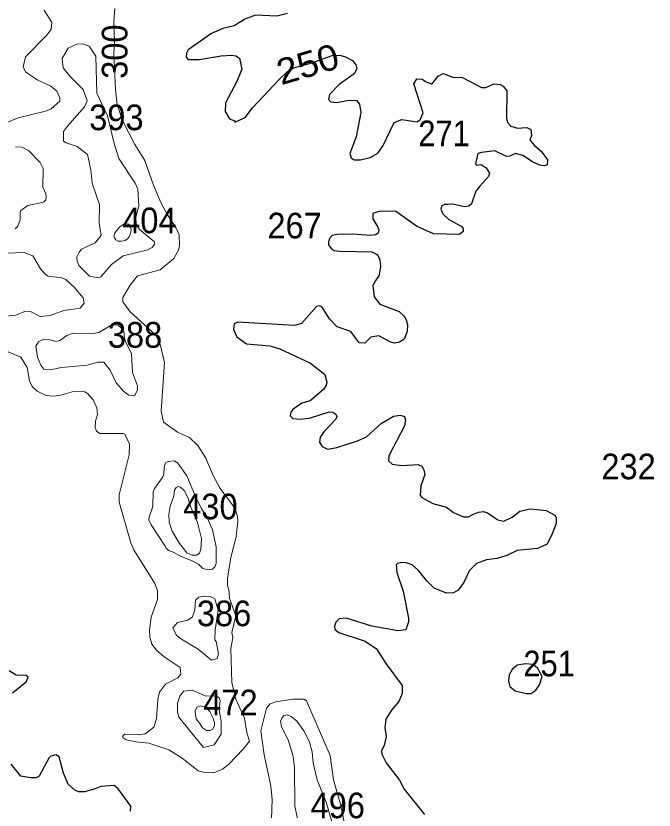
# Model space of a CAD drawing. Extents: x 499.9 to 555.3, y 9281.5 to 9336.8.
# Drawn here: x 510.006 to 513.988, y 9318.021 to 9322.977 of the extents above; entities that cross this region are included whole.
import ezdxf
from ezdxf.enums import TextEntityAlignment as Align

# ---------------------------------------------------------------- set-up
doc = ezdxf.new("R2010")
doc.units = 0
doc.header["$LTSCALE"] = 0.064
doc.layers.add('1', color=7, linetype='Continuous', lineweight=25)
doc.layers.add('2', color=7, linetype='Continuous', lineweight=13)
doc.layers.add('21', color=7, linetype='Continuous')
doc.layers.add('61', color=7, linetype='Continuous')

msp = doc.modelspace()

# ---------------------------------------------------------------- linework, layer by layer
at = {"layer": '1'}
for points in [[(511.7005, 9322.9921), (511.6328, 9322.9747), (511.5, 9322.9823), (511.4339, 9322.9573), (511.3669, 9322.9146), (511.2963, 9322.8996), (511.227, 9322.8667), (511.08, 9322.7658), (511.0698, 9322.7458), (511.0678, 9322.7203), (511.0805, 9322.7061), (511.1101, 9322.7058), (511.1499, 9322.7057), (511.2859, 9322.7292), (511.3514, 9322.7325), (511.3783, 9322.7279), (511.3998, 9322.7128), (511.4152, 9322.6445), (511.3837, 9322.5687), (511.3124, 9322.435), (511.3123, 9322.3802), (511.3385, 9322.3346), (511.3715, 9322.3222), (511.3721, 9322.3147), (511.4355, 9322.3441), (511.4815, 9322.4039), (511.6482, 9322.5815), (511.7006, 9322.6314), (511.7379, 9322.6543), (511.8526, 9322.6844), (511.9787, 9322.7308), (512.0276, 9322.7317), (512.0625, 9322.7222), (512.1062, 9322.6986), (512.1261, 9322.6727), (512.1321, 9322.6467), (512.1163, 9322.616), (512.0229, 9322.5493), (511.9632, 9322.4876), (511.9556, 9322.4558), (511.9703, 9322.4408), (512.0085, 9322.437), (512.0824, 9322.4508), (512.1299, 9322.4493), (512.1497, 9322.4261)], [(512.1163, 9322.0794), (512.1565, 9322.0789), (512.2161, 9322.093), (512.2646, 9322.1212), (512.2973, 9322.1677), (512.3656, 9322.3116), (512.4144, 9322.3313), (512.5066, 9322.316), (512.529, 9322.3298), (512.5466, 9322.3734), (512.4878, 9322.5543), (512.5065, 9322.5847), (512.5407, 9322.5828), (512.5648, 9322.5656), (512.6002, 9322.552), (512.6412, 9322.6003), (512.672, 9322.6176), (512.7319, 9322.5945), (512.7923, 9322.5939), (512.9101, 9322.5308), (512.9371, 9322.5308), (512.9872, 9322.5527), (513.027, 9322.5496), (513.0468, 9322.5399), (513.0694, 9322.5092), (513.0661, 9322.3386), (513.0727, 9322.3128), (513.0937, 9322.2897), (513.1361, 9322.2761), (513.1926, 9322.2807), (513.2183, 9322.2675), (513.2218, 9322.2314), (513.2117, 9322.2021), (513.2412, 9322.1677), (513.2834, 9322.1331), (513.3217, 9322.0792), (513.3199, 9322.0483), (513.3032, 9322.0422), (513.2754, 9322.0457), (513.2286, 9322.0665), (513.1693, 9322.1071), (513.1234, 9322.1179), (513.0858, 9322.1013), (513.0667, 9322.101), (512.9944, 9322.1356), (512.911, 9322.1251), (512.8885, 9322.1186), (512.8734, 9322.054), (512.8805, 9322.0458), (512.908, 9322.0502), (512.9392, 9322.0291), (512.9601, 9321.9951), (512.9542, 9321.9744), (512.9002, 9321.9139), (512.8745, 9321.8836), (512.8493, 9321.8045), (512.8316, 9321.7893), (512.8051, 9321.7859), (512.7319, 9321.803), (512.7008, 9321.8014), (512.6804, 9321.8009), (512.6622, 9321.7925), (512.6571, 9321.7722), (512.6696, 9321.7413), (512.7064, 9321.7077), (512.7846, 9321.6654), (512.7961, 9321.6515), (512.7966, 9321.6314), (512.773, 9321.6142), (512.6117, 9321.6169), (512.5059, 9321.6648), (512.3743, 9321.7598), (512.2703, 9321.7569), (512.2326, 9321.7439), (512.2326, 9321.7118), (512.2643, 9321.6587), (512.2696, 9321.641), (512.2667, 9321.6209), (512.2484, 9321.6115), (512.2178, 9321.6066), (512.1079, 9321.6154), (512.0103, 9321.6126), (511.9793, 9321.608), (511.9616, 9321.5891), (511.9551, 9321.5684), (511.9563, 9321.5478), (511.9734, 9321.5265), (511.9911, 9321.5135), (512.0285, 9321.5084), (512.2242, 9321.5053), (512.2497, 9321.4957), (512.2643, 9321.4834), (512.2758, 9321.4558), (512.2815, 9321.4135), (512.2722, 9321.3587)], [(512.1497, 9322.4261), (512.1578, 9322.3752), (512.1286, 9322.2228), (512.0893, 9322.1191), (512.0975, 9322.0927), (512.1163, 9322.0794)], [(512.2722, 9321.3587), (512.2505, 9321.3278), (512.2323, 9321.2945), (512.2417, 9321.2238), (512.2769, 9321.178), (512.3974, 9321.1329)], [(512.3974, 9321.1329), (512.4273, 9321.1034), (512.4413, 9321.0804), (512.4485, 9321.0496), (512.4479, 9321.0075), (512.4291, 9320.9599), (512.3987, 9320.9421), (512.3673, 9320.936), (512.3458, 9320.9414), (512.271, 9320.9816), (512.2196, 9320.972), (512.1832, 9320.9348), (512.147, 9320.9375), (512.0949, 9321.0072), (512.0094, 9321.0379), (511.9632, 9321.0871), (511.9374, 9321.1263), (511.9162, 9321.1604), (511.9015, 9321.1677), (511.8803, 9321.1641), (511.7885, 9321.0574), (511.7436, 9321.0445), (511.3892, 9321.0652), (511.3667, 9321.0548), (511.3634, 9321.0207), (511.3835, 9320.9748), (511.4451, 9320.9311), (511.5898, 9320.918), (511.6527, 9320.9006), (511.8444, 9320.8111), (511.9326, 9320.7399), (511.9453, 9320.6908), (511.9419, 9320.6725), (511.9242, 9320.6456), (511.8419, 9320.5756), (511.7897, 9320.56), (511.7347, 9320.5239), (511.7204, 9320.5042), (511.7169, 9320.4814), (511.7332, 9320.4648), (511.7746, 9320.4601), (511.8365, 9320.4678), (511.9607, 9320.5057), (511.9836, 9320.5042), (512.0023, 9320.4929), (512.0074, 9320.4783), (512.0016, 9320.4616), (511.9298, 9320.385), (511.9038, 9320.3478), (511.8989, 9320.3172), (511.9162, 9320.2908), (511.9424, 9320.2771), (511.9528, 9320.274), (512.0084, 9320.2847), (512.1373, 9320.325), (512.1937, 9320.3502), (512.2855, 9320.4339), (512.362, 9320.4801), (512.4039, 9320.4851), (512.4294, 9320.4778), (512.4371, 9320.4551), (512.4293, 9320.4202), (512.3333, 9320.2311), (512.331, 9320.2014), (512.3532, 9320.1801), (512.4126, 9320.1708), (512.516, 9320.1786), (512.5374, 9320.1669), (512.5502, 9320.1443), (512.5562, 9320.1165), (512.5329, 9320.0443), (512.5284, 9319.9841), (512.5378, 9319.9714), (512.6077, 9319.9348), (512.692, 9319.9122), (512.7351, 9319.8775), (512.7987, 9319.8506), (512.8289, 9319.8506), (512.8616, 9319.868), (512.8922, 9319.8807), (512.9228, 9319.8849), (512.9485, 9319.876), (512.9872, 9319.85), (513.0134, 9319.8328), (513.0501, 9319.8253), (513.101, 9319.8489), (513.149, 9319.8867), (513.2171, 9319.9023), (513.3142, 9319.892), (513.3682, 9319.8613), (513.3772, 9319.8467), (513.3764, 9319.8107), (513.3525, 9319.7454), (513.3198, 9319.6814), (513.261, 9319.6534)], [(513.261, 9319.6534), (513.1338, 9319.6419), (513.0692, 9319.61), (513.0055, 9319.591), (512.9412, 9319.5826), (512.8791, 9319.5608)], [(512.8791, 9319.5608), (512.8338, 9319.5144), (512.8013, 9319.4423), (512.7646, 9319.3937), (512.735, 9319.3763), (512.6917, 9319.3752), (512.6153, 9319.4071), (512.57, 9319.4519), (512.5185, 9319.5176), (512.478, 9319.5513), (512.4414, 9319.564), (512.4108, 9319.5662), (512.3861, 9319.5601), (512.3787, 9319.5518), (512.3822, 9319.5039), (512.421, 9319.3872), (512.4561, 9319.2189), (512.4547, 9319.1962), (512.4379, 9319.1454), (512.3904, 9319.1407), (512.227, 9319.1697), (512.0665, 9319.2198), (512.0217, 9319.2145), (512.002, 9319.1952), (511.9939, 9319.1698), (511.9957, 9319.1481), (512.0196, 9319.1291), (512.1843, 9319.0751), (512.2563, 9319.0269), (512.3144, 9318.936), (512.4163, 9318.7982), (512.4164, 9318.7491), (512.3946, 9318.6988), (512.3499, 9318.6455), (512.3135, 9318.5897), (512.307, 9318.5357), (512.3162, 9318.4816), (512.3035, 9318.4244), (512.2865, 9318.394), (512.2893, 9318.3709), (512.3154, 9318.3156), (512.3986, 9318.2085), (512.429, 9318.1522), (512.5546, 9317.9936)], [(509.9834, 9318.7536), (510.07, 9318.8218), (510.0812, 9318.8516), (510.0704, 9318.861), (510.0064, 9318.864), (509.9626, 9318.8909)], [(510.3986, 9318.1364), (510.3732, 9318.1459), (510.3315, 9318.1832), (510.3032, 9318.2524), (510.2749, 9318.354), (510.2543, 9318.3665), (510.2232, 9318.3581), (510.2114, 9318.3457), (510.1514, 9318.2339), (510.1318, 9318.2224), (510.0962, 9318.2222), (510.0359, 9318.2337), (509.9751, 9318.3073)], [(510.6447, 9318.1551), (510.6181, 9318.1757), (510.5345, 9318.1697), (510.4941, 9318.1522), (510.4329, 9318.1363), (510.3986, 9318.1364)], [(510.7214, 9318.0154), (510.723, 9318.0464), (510.6447, 9318.1551)]]:
    msp.add_lwpolyline(points, dxfattribs=at)
msp.add_lwpolyline([(513.2898, 9318.8542), (513.2616, 9318.906), (513.2339, 9318.9296), (513.1846, 9318.9343), (513.1335, 9318.9263), (513.1028, 9318.8987), (513.0834, 9318.8654), (513.0799, 9318.828), (513.0883, 9318.7928), (513.1203, 9318.7666), (513.1894, 9318.7492), (513.2181, 9318.7491), (513.2493, 9318.7689), (513.2719, 9318.8034)], close=True, dxfattribs=at)
at = {"layer": '2'}
for points in [[(510.1823, 9323.0126), (510.2292, 9322.9355), (510.2248, 9322.8935), (510.1947, 9322.852), (510.0645, 9322.7209), (510.0502, 9322.6602), (510.0646, 9322.6277), (510.139, 9322.5776), (510.2235, 9322.5383), (510.261, 9322.5086), (510.2795, 9322.4661), (510.2801, 9322.4457), (510.225, 9322.397), (510.191, 9322.3823), (510.0191, 9322.3409), (509.856, 9322.2749)], [(510.748, 9322.1758), (510.6723, 9322.3209), (510.6369, 9322.4223), (510.6268, 9322.5159), (510.6158, 9322.7446), (510.6216, 9322.8126), (510.6159, 9322.9429), (510.6236, 9323.0244)], [(511.0036, 9321.6576), (510.9521, 9321.7354), (510.9103, 9321.8128), (510.864, 9321.9209), (510.8104, 9322.076), (510.748, 9322.1758)], [(510.004, 9322.1595), (510.0452, 9322.1579), (510.0834, 9322.1373), (510.1565, 9322.0626), (510.1756, 9322.0261), (510.1742, 9321.9081), (510.192, 9321.8674), (510.1944, 9321.8469), (510.192, 9321.8291), (510.1781, 9321.8159), (510.081, 9321.7937), (510.036, 9321.7623), (510.0316, 9321.7506), (510.0324, 9321.7052), (510.0176, 9321.6659), (510.0019, 9321.6482)], [(510.2355, 9320.6048), (510.2776, 9320.6096), (510.3643, 9320.6334), (510.4349, 9320.631), (510.4527, 9320.6205), (510.487, 9320.5814), (510.5098, 9320.5315), (510.5144, 9320.4911), (510.5022, 9320.4495), (510.5005, 9320.4092), (510.5089, 9320.3871), (510.5285, 9320.3709), (510.6728, 9320.3721), (510.6849, 9320.3672), (510.7137, 9320.3056), (510.7121, 9320.2387), (510.6504, 9319.989), (510.6501, 9319.9434), (510.723, 9319.6888), (510.7416, 9319.6451), (510.8718, 9319.4349), (510.8885, 9319.3919), (510.8885, 9319.3362), (510.8506, 9319.2264), (510.8398, 9319.147), (510.8413, 9319.1016), (510.8541, 9319.0567), (510.882, 9319.0201), (510.9317, 9318.9779), (511.0309, 9318.9105), (511.0353, 9318.8691), (511.0154, 9318.8473), (510.9398, 9318.8076), (510.902, 9318.7574), (510.892, 9318.7139), (510.8827, 9318.5916), (510.8659, 9318.5399), (510.813, 9318.4964), (510.771, 9318.4912), (510.6859, 9318.4957), (510.6767, 9318.4895), (510.6717, 9318.4801), (510.6747, 9318.4722), (510.6926, 9318.4609), (510.7511, 9318.4469), (510.8354, 9318.44), (510.9588, 9318.3972), (511.0423, 9318.3459), (511.1435, 9318.2669), (511.1754, 9318.2583), (511.2413, 9318.254), (511.2946, 9318.2779), (511.335, 9318.3071), (511.4245, 9318.4011), (511.4628, 9318.4514), (511.4457, 9318.5032), (511.4313, 9318.5948), (511.3772, 9318.7147), (511.3537, 9318.8183), (511.3472, 9319.0291), (511.3597, 9319.0968), (511.3522, 9319.1294), (511.3787, 9319.2329), (511.3378, 9319.3447), (511.3373, 9319.3821), (511.3249, 9319.4278), (511.3249, 9319.4683), (511.347, 9319.5981), (511.379, 9319.727), (511.3834, 9319.7675), (511.3898, 9319.8201), (511.3885, 9319.8527), (511.3728, 9319.9036), (511.28, 9320.0293), (511.2393, 9320.1044), (511.1887, 9320.2212), (511.1418, 9320.296), (511.0883, 9320.3464), (511.0134, 9320.3788), (510.9268, 9320.4432), (510.9128, 9320.511), (510.9333, 9320.8141), (510.9048, 9320.9287), (510.8757, 9320.9863), (510.7177, 9321.1306), (510.6726, 9321.1936), (510.6734, 9321.2207), (510.7195, 9321.297), (510.7636, 9321.3546), (510.9061, 9321.3936), (510.9905, 9321.4643), (511.0193, 9321.516), (511.0257, 9321.5455), (511.0252, 9321.611), (511.0036, 9321.6576)], [(509.8911, 9321.4945), (510.0562, 9321.5008), (510.1114, 9321.4801), (510.1595, 9321.3981), (510.1896, 9321.363), (510.2069, 9321.3543), (510.2917, 9321.3419), (510.317, 9321.3327), (510.3686, 9321.2841), (510.4261, 9321.2171), (510.4315, 9321.1842), (510.4056, 9321.1539), (510.3055, 9321.1393), (510.2202, 9321.1071), (510.1567, 9321.1016), (510.1, 9321.1311), (510.0651, 9321.1345), (510.0062, 9321.1108), (509.9244, 9321.1011)], [(509.9332, 9320.8917), (510.0361, 9320.8475), (510.0768, 9320.783)], [(510.0768, 9320.783), (510.0898, 9320.701), (510.1064, 9320.6642), (510.1393, 9320.6353), (510.1949, 9320.6081), (510.2355, 9320.6048)], [(511.818, 9318.7042), (511.8029, 9318.7135), (511.734, 9318.7141), (511.628, 9318.6965), (511.593, 9318.6839), (511.5695, 9318.6579), (511.5336, 9318.5169), (511.5539, 9318.3673), (511.5953, 9318.1704), (511.6049, 9318.09), (511.5937, 9317.7772)], [(512.0536, 9317.9453), (512.0301, 9318.0575), (511.987, 9318.211), (511.9666, 9318.3621), (511.818, 9318.7042)], [(511.9787, 9317.9411), (511.9423, 9318.071), (511.8853, 9318.2103), (511.8613, 9318.3161), (511.8532, 9318.3861), (511.8347, 9318.4514), (511.8027, 9318.516), (511.7588, 9318.576), (511.7232, 9318.6053), (511.6983, 9318.6152), (511.6771, 9318.6111), (511.664, 9318.5944), (511.657, 9318.5771), (511.6621, 9318.5435), (511.7062, 9318.4545), (511.7356, 9318.3557), (511.7433, 9318.2882), (511.7451, 9318.0463), (511.7848, 9317.8632)]]:
    msp.add_lwpolyline(points, dxfattribs=at)
for points in [[(510.6188, 9322.1803), (510.5774, 9322.3547), (510.5106, 9322.4959), (510.5042, 9322.7258), (510.4621, 9322.7889), (510.424, 9322.8024), (510.3851, 9322.8008), (510.3313, 9322.7766), (510.2938, 9322.7119), (510.2998, 9322.6524), (510.3413, 9322.6006), (510.4243, 9322.5185), (510.4495, 9322.4472), (510.4346, 9322.4105), (510.327, 9322.2901), (510.3025, 9322.255), (510.3034, 9322.1965), (510.3185, 9322.1849), (510.3878, 9322.1633), (510.4528, 9322.1126), (510.4741, 9322.0169), (510.4816, 9321.9346), (510.5267, 9321.8007), (510.526, 9321.6835), (510.5374, 9321.6079), (510.5005, 9321.5621), (510.4158, 9321.5211), (510.3994, 9321.5024), (510.386, 9321.473), (510.3875, 9321.446), (510.3987, 9321.4203), (510.4657, 9321.3529), (510.5188, 9321.3434), (510.536, 9321.3501), (510.6012, 9321.4264), (510.6757, 9321.4792), (510.8283, 9321.5184), (510.8568, 9321.5327), (510.8712, 9321.5524), (510.8701, 9321.5669), (510.7763, 9321.6451), (510.7567, 9321.6775), (510.7534, 9321.7205), (510.7723, 9321.7921), (510.7666, 9321.8954), (510.7498, 9321.9328), (510.6472, 9322.0875)], [(510.6434, 9321.572), (510.6653, 9321.5707), (510.6866, 9321.5768), (510.7023, 9321.5864), (510.7133, 9321.5981), (510.7215, 9321.62), (510.725, 9321.644), (510.7195, 9321.6667), (510.7092, 9321.6776), (510.6955, 9321.6804), (510.6783, 9321.6769), (510.6564, 9321.6639), (510.6399, 9321.644), (510.6228, 9321.6207), (510.6166, 9321.6029), (510.62, 9321.5919), (510.6296, 9321.5796)], [(510.5551, 9320.8158), (510.516, 9320.8159), (510.448, 9320.7969), (510.2898, 9320.7828), (510.2184, 9320.7685), (510.1795, 9320.7729), (510.1617, 9320.797), (510.1412, 9320.8473), (510.1302, 9320.9164), (510.1474, 9320.9435), (510.1761, 9320.9578), (510.2191, 9320.9563), (510.2553, 9320.9459), (510.2797, 9320.9519), (510.3224, 9320.9834), (510.3628, 9320.9975), (510.4885, 9320.9964), (510.5228, 9321.0021), (510.5928, 9321.0438), (510.6188, 9321.0498), (510.6447, 9321.0476), (510.6674, 9321.0275), (510.6791, 9321.0108), (510.6826, 9320.9642), (510.6882, 9320.9494), (510.726, 9320.8696), (510.7341, 9320.7529), (510.7644, 9320.6684), (510.7645, 9320.6422), (510.7446, 9320.6067), (510.7106, 9320.6114), (510.6793, 9320.6345), (510.632, 9320.6881), (510.5942, 9320.7671)], [(510.9327, 9319.6746), (510.9423, 9319.6563), (510.9584, 9319.6414), (510.9819, 9319.6322), (511.0386, 9319.6039), (511.1094, 9319.5756), (511.1448, 9319.5558), (511.173, 9319.5294), (511.2075, 9319.52), (511.2326, 9319.5246), (511.2468, 9319.5402), (511.2542, 9319.5597), (511.2557, 9319.6639), (511.2326, 9319.7696), (511.193, 9319.8592), (511.1638, 9319.9019), (511.1231, 9319.9833), (511.0721, 9320.1075), (511.0166, 9320.1854), (510.9946, 9320.2002), (510.9557, 9320.1972), (510.9392, 9320.1892), (510.9304, 9320.1598), (510.9281, 9320.1203), (510.9225, 9320.1011), (510.8825, 9320.0445), (510.87, 9320.0274), (510.863, 9320.0062), (510.8599, 9319.9196), (510.8545, 9319.8971), (510.8375, 9319.8518), (510.8358, 9319.8325), (510.85, 9319.8009)], [(510.9805, 9319.7611), (511.0259, 9319.6847), (511.0725, 9319.626), (511.106, 9319.6116), (511.1354, 9319.6131), (511.1519, 9319.6252), (511.1599, 9319.6473), (511.1632, 9319.7158), (511.1377, 9319.8164), (511.098, 9319.9118), (511.0783, 9319.9722), (511.0545, 9320.015), (511.0329, 9320.0373), (511.0174, 9320.0402), (511.0066, 9320.0342), (510.9947, 9320.0175), (510.9919, 9319.9807), (510.9684, 9319.9189), (510.9593, 9319.8674), (510.9621, 9319.8178)], [(511.2547, 9319.0734), (511.2458, 9319.0848), (511.2488, 9319.1472), (511.2678, 9319.2685), (511.2469, 9319.3393), (511.2185, 9319.3552), (511.1803, 9319.3569), (511.1469, 9319.3504), (511.126, 9319.3323), (511.1224, 9319.2718), (511.1077, 9319.2275), (511.0789, 9319.207), (511.0138, 9319.1921), (510.9858, 9319.1594), (511.0063, 9319.1159), (511.0286, 9319.0934), (511.1434, 9319.0259), (511.2259, 9318.958), (511.2608, 9318.9675), (511.2687, 9318.9957)], [(511.2428, 9318.4294), (511.2869, 9318.4949), (511.2855, 9318.5769), (511.2745, 9318.6479), (511.2805, 9318.7061), (511.2744, 9318.7222), (511.2573, 9318.733), (511.1863, 9318.7352), (511.1052, 9318.7693), (511.0518, 9318.7633), (511.029, 9318.7329), (511.0147, 9318.6885), (511.013, 9318.6324), (511.023, 9318.6019), (511.1765, 9318.4131)], [(511.153, 9318.5616), (511.1698, 9318.535), (511.1955, 9318.5192), (511.2183, 9318.5182), (511.2351, 9318.5271), (511.244, 9318.5488), (511.244, 9318.5686), (511.2361, 9318.5962), (511.2163, 9318.6367), (511.1866, 9318.6644), (511.157, 9318.6723), (511.1353, 9318.6644), (511.1244, 9318.6417), (511.1254, 9318.617), (511.1313, 9318.5903)]]:
    msp.add_lwpolyline(points, close=True, dxfattribs=at)

# ---------------------------------------------------------------- texts
at = {"layer": '21'}
for s, width, p in [('393', 0.95, (510.463, 9322.2642)), ('271', 0.9, (512.5165, 9322.1643)), ('404', 0.95, (510.669, 9321.6213)), ('267', 0.95, (511.575, 9321.5889)), ('388', 0.95, (510.5795, 9320.9069)), ('232', 0.95, (513.6588, 9320.0858)), ('430', 0.95, (511.0497, 9319.8361)), ('386', 0.95, (511.135, 9319.169)), ('251', 0.9, (513.1719, 9318.8562)), ('472', 0.95, (511.1746, 9318.6128)), ('496', 0.95, (511.8443, 9317.9708))]:
    msp.add_text(s, height=0.16, dxfattribs=dict(at, width=width)).set_placement(p)
at = {"layer": '61'}
for s, rotation, width, p in [('300', 90, 0.95, (510.7016, 9322.7543)), ('250', 16.526, 1.1, (511.8489, 9322.5998))]:
    msp.add_text(s, height=0.16, rotation=rotation, dxfattribs=dict(at, width=width)).set_placement(p, align=Align.CENTER)

doc.saveas('drawing.dxf')
